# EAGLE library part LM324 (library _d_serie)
LM324 - quad OpAmp
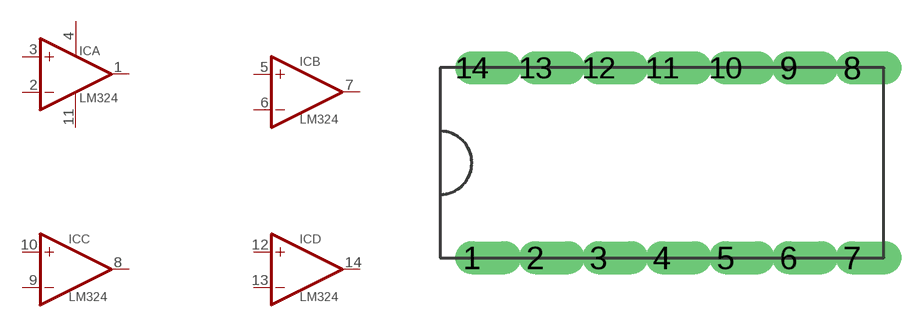
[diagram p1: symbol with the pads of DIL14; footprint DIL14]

Designator prefix IC; gates A=OPAMP+- B=OPAMP C=OPAMP D=OPAMP

## LM324  [DIL14]
1  A:OUT  out
2  A:-IN  in
3  A:+IN  in
4  A:V+  pwr
5  B:+IN  in
6  B:-IN  in
7  B:OUT  out
8  C:OUT  out
9  C:-IN  in
10  C:+IN  in
11  A:GND  pwr
12  D:+IN  in
13  D:-IN  in
14  D:OUT  out

## Footprint DIL14 (pad centres in mm)
Dual-In-Line, 14 pins
drill 0.813 offset: 1 -7.62,-3.81; 2 -5.08,-3.81; 3 -2.54,-3.81; 4 0,-3.81; 5 2.54,-3.81; 6 5.08,-3.81; 7 7.62,-3.81; 8 7.62,3.81; 9 5.08,3.81; 10 2.54,3.81; 11 0,3.81; 12 -2.54,3.81; 13 -5.08,3.81; 14 -7.62,3.81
